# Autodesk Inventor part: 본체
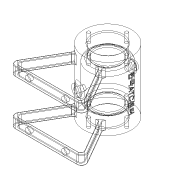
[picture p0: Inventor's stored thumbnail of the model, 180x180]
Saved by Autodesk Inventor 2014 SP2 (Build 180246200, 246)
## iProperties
Created: 2016-03
Part Number: 본체
Material: 일반
Document SubType Name: Modeling
Designer: 손기택
Density: 1 g/cm^3
Appearance: 기본값
Author: 손기택
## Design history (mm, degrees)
sketch "스케치1"
  geometry: C1 r 26 at (0, 0); 1 further point
  constraints: 1 centre point, 1 coincident
  dimensions: "d0" = 52 diameter of C1
extrude "돌출1" new body sketch "스케치1" stored distance "d1" = 70; taper "d2" = 0 deg
sketch "스케치2"
  geometry: L1 (13, -22.517)-(37.528, -65); L2 (0, 0)-(100, 0); L3 (0, 0)-(105.078, 0); L4 (0, -65)-(37.528, -65); L5 (42.724, -68)-(13.224, -16.905); L6 (0, -68)-(42.724, -68); L7 (0, -16)-(0, -80); L8 (-13, -22.517)-(-37.528, -65); L9 (0, -68)-(-42.724, -68); L10 (0, -65)-(-37.528, -65); L11 (-42.724, -68)-(-13.224, -16.905); C1 r 26 at (0, 0) reference; A1 r 26 centre (0, 0) between (-13, -22.517) and (13, -22.517); A2 r 26 centre (0, 0) between (-15.511, -20.866) and (15.511, -20.866); 6 further points
  constraints: 22 end point, 8 point on circle, 4 point on line, 4 symmetric about line, 2 centre point, 2 coincident, 2 horizontal, 1 perpendicular
  dimensions: "d4" = 60 deg angle of L1 L2; "d73" = 65 distance from line of L4 point (0, 0); "d107" = 3 distance between parallel lines of L5 L1; "d108" = 3 distance between parallel lines of L6 L4
sketch "스케치4"
  geometry: C1 r 16 at (0, 0); 1 further point
  constraints: 1 centre point, 1 coincident
  dimensions: "d11" = 32 diameter of C1
extrude "돌출4" cut sketch "스케치4" distance "d12" = 12; taper "d13" = 0 deg
sketch "스케치5"
  geometry: C1 r 14 at (0, 0); 1 further point
  constraints: 1 centre point, 1 coincident
  dimensions: "d14" = 28 diameter of C1
extrude "돌출5" cut sketch "스케치5" distance "d15" = 2; taper "d16" = 0 deg
sketch "스케치6"
  geometry: C1 r 21 at (0, 0); 1 further point
  constraints: 1 centre point, 1 coincident
  dimensions: "d17" = 42 diameter of C1
extrude "돌출6" cut sketch "스케치6" distance "d18" = 42; taper "d19" = 0 deg
chamfer "모따기1" distance "d20" = 1; stored, may be unused: second distance "d21" = 2, angle "d22" = 45 deg
fillet "모깎기1" dims "d23" = 3
sketch "스케치7"
  geometry: C1 r 26 at (0, 0) reference; 2 further points
  dimensions: "d24" = 21 distance of point (0, 0) point (0, 21)
hole "구멍1" sketch "스케치7" at (0, 21) diameter "d25" = 3.242; stored, may be unused: countersink angle "d29" = 90 deg, drill point angle "d31" = 118 deg; dims "d26" = 8, "d27" = 4, "d28" = 2, "d30" = 10
node "작업 평면1"
sketch "스케치8"
  geometry: L1 (3.002, 29.901)-(3.002, -29.901); L2 (3.002, -29.901)-(-3.002, -29.901); L3 (-3.002, -29.901)-(-3.002, 29.901); L4 (-3.002, 29.901)-(3.002, 29.901); L5 (-26, -35)-(26, -35) reference; L6 (26, 35)-(-26, 35) reference; 3 further points
  constraints: 2 midpoint, 1 horizontal alignment, 1 vertical alignment, 2 other
feature "엠보싱1" sketch "스케치8" dims "d36" = 0.5, "d37" = 0
node "작업 평면2"
sketch "스케치9"
  geometry: C1 r 5 at (0, 0); 1 further point
  constraints: 1 centre point, 1 coincident
  dimensions: "d39" = 10 diameter of C1
extrude "돌출7" join sketch "스케치9" stored distance "d40" = 42; taper "d41" = 0 deg
sketch "스케치10"
  geometry: 2 further points
  constraints: 1 coincident
hole "구멍2" sketch "스케치10" at (0, 0) diameter "d42" = 5.188; stored, may be unused: countersink angle "d46" = 90 deg, drill point angle "d48" = 0 deg; dims "d43" = 9, "d44" = 4, "d45" = 2, "d47" = 9
sketch "스케치11"
  geometry: L1 (0, 0)-(29, 0); 1 further point
  constraints: 2 end point, 1 horizontal
node "작업 평면3"
node "작업 평면4"
fillet "모깎기4" dims "d85" = 2
fillet "모깎기5" dims "d86" = 0.3
sketch "스케치17"
  geometry: L1 (0, 0)-(26, 0); 1 further point
  constraints: 2 end point, 1 horizontal
node "작업 평면5"
node "작업 평면6"
sketch "스케치18"
  geometry: C1 r 6 at (0, 0); 1 further point
  constraints: 1 centre point, 1 coincident
  dimensions: "d97" = 12 diameter of C1
extrude "돌출13" join sketch "스케치18" stored distance "d98" = 40; taper "d99" = 0 deg
sketch "스케치19"
  geometry: 2 further points
  constraints: 1 coincident
hole "구멍4" sketch "스케치19" at (0, 0) diameter "d100" = 5.188; stored, may be unused: countersink angle "d104" = 90 deg, drill point angle "d106" = 0 deg; dims "d101" = 9, "d102" = 4, "d103" = 2, "d105" = 9
extrude "돌출14" join sketch "스케치2" stored distance "d110" = 60; taper "d111" = 0 deg
sketch "스케치21"
  geometry: L1 (-37.528, -65)-(-13, -22.517) reference; L2 (-15.511, -20.866)-(-42.724, -68) reference; L3 (-42.724, -68)-(42.724, -68) reference; L4 (42.724, -68)-(15.511, -20.866) reference; L5 (13, -22.517)-(37.528, -65) reference; L6 (37.528, -65)-(-37.528, -65) reference; A1 r 26 centre (0, 0) between (-15.511, -20.866) and (-13, -22.517) reference; A2 r 26 centre (0, 0) between (13, -22.517) and (15.511, -20.866) reference; 1 further point
extrude "돌출15" cut sketch "스케치21" stored distance "d112" = 40; taper "d113" = 0 deg
fillet "모깎기13" dims "d114" = 5
fillet "모깎기14" dims "d115" = 2
fillet "모깎기15" dims "d116" = 3
fillet "모깎기16" dims "d117" = 3
fillet "모깎기17" dims "d118" = 3
fillet "모깎기18" dims "d119" = 0.5
fillet "모깎기19" dims "d120" = 0.5
sketch "스케치22"
  geometry: L1 (0, 0)-(64.663, 0) reference; L2 (0, -9)-(0, 0) reference; L3 (64.663, -9)-(0, -9) reference; L4 (64.663, 0)-(64.663, -9) reference; L5 (30.711, -4.5)-(33.953, -4.5) reference; L6 (30.711, -4.5)-(33.953, -4.5) reference; L7 (9.711, -4.5)-(12.953, -4.5) reference; C1 r 3 at (12.332, -4.5); C2 r 3 at (52.332, -4.5); 1 further point
  constraints: 2 centre point
  dimensions: "d123" = 6 diameter of C1; "d124" = 6 diameter of C2
extrude "돌출16" cut sketch "스케치22" stored distance "d125" = 10; taper "d126" = 0 deg
node "솔리드1"
mirror "대칭1"
pattern_circular "원형 패턴1" dims angle "d33" = 360 deg
mirror "대칭2"
mirror "대칭5"
node "투영된 루프2"
node "투영된 루프6"
node "투영된 루프7"
other parameters: "d35" = 26, "d38" = 29, "d51" = 3, "d96" = 3
